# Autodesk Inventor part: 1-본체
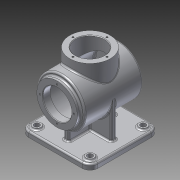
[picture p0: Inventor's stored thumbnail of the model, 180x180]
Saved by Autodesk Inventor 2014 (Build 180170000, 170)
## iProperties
Created: 2015-07
Part Number: 1-본체
Material: 알루미늄 6061
Document SubType Name: Modeling
Designer: Owner
Density: 2.71 g/cm^3
Appearance: 알루미늄 - 평지
Mass: 1277.64 g
Surface Area: 1267.64 cm^2
Volume: 471.455 cm^3
Author: Owner
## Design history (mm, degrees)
sketch "스케치1"
  geometry: C1 r 45 at (0, 0); 1 further point
  constraints: 1 centre point, 1 coincident
  dimensions: "d0" = 90 diameter of C1
extrude "돌출1" new body sketch "스케치1" stored distance "d1" = 110; taper "d2" = 0 deg
sketch "스케치2"
  geometry: C1 r 45 at (0, 0) reference; C2 r 38 at (0, 0)
  constraints: 1 centre point, 1 coincident
  dimensions: "d3" = 76 diameter of C2
extrude "돌출2" join sketch "스케치2" distance "d4" = 7; taper "d5" = 0 deg
node "작업 평면1"
sketch "스케치3"
  geometry: L1 (-65, 65)-(65, 65); L2 (65, 65)-(65, -65); L3 (65, -65)-(-65, -65); L4 (-65, -65)-(-65, 65); 3 further points
  constraints: 8 end point, 2 midpoint, 2 parallel, 1 horizontal, 1 horizontal alignment, 1 perpendicular, 1 vertical alignment
  dimensions: "d7" = 130 distance of L2.end L3.end; "d8" = 130 distance of L3.end L1.start
extrude "돌출3" join sketch "스케치3" distance "d9" = 10; taper "d10" = 0 deg
sketch "스케치4"
  geometry: L1 (-65, 65)-(-65, -65) reference; L2 (-45, 5)-(-5, 5); L3 (-5, 5)-(-5, 45); L4 (-5, 45)-(5, 45); L5 (5, 45)-(5, 5); L6 (5, 5)-(45, 5); L7 (45, 5)-(45, -5); L8 (45, -5)-(5, -5); L9 (5, -5)-(5, -45); L10 (5, -45)-(-5, -45); L11 (-5, -45)-(-5, -5); L12 (-5, -5)-(-45, -5); L13 (-45, -5)-(-45, 5); 4 further points
  constraints: 24 end point, 8 parallel, 7 equal length, 3 midpoint, 2 collinear, 2 perpendicular, 2 vertical alignment, 1 horizontal alignment
  dimensions: "d11" = 10 distance of L3.end L4.end; "d12" = 90 distance between parallel lines of L7 L13
extrude "돌출4" join sketch "스케치4" stored distance "d13" = 10; taper "d14" = 0 deg
sketch "스케치5"
  geometry: C1 r 7.5 at (-50, 50); C2 r 7.5 at (-50, -50); C3 r 7.5 at (50, -50); C4 r 7.5 at (50, 50); 1 further point
  constraints: 4 centre point, 2 horizontal alignment, 2 vertical alignment
  dimensions: "d15" = 15 diameter of C1; "d16" = 15 diameter of C2; "d17" = 15 diameter of C3; "d18" = 15 diameter of C4; "d19" = 100 distance of C4.centre C1.centre; "d20" = 50 horizontal distance of C4.centre point (0, 0); "d21" = 100 distance of C2.centre C1.centre; "d22" = 50 horizontal distance of point (0, 0) C1.centre
extrude "돌출5" join sketch "스케치5" distance "d23" = 3; taper "d24" = 0 deg
hole "구멍1" diameter "d27" = 10; stored, may be unused: countersink angle "d31" = 90 deg, drill point angle "d33" = 118 deg; dims "d25" = 10, "d26" = 10, "d28" = 6, "d29" = 4, "d30" = 2, "d32" = 8
hole "구멍2" diameter "d36" = 10; stored, may be unused: countersink angle "d40" = 90 deg, drill point angle "d42" = 118 deg; dims "d34" = 10, "d35" = 10, "d37" = 6, "d38" = 4, "d39" = 2, "d41" = 8
hole "구멍3" diameter "d45" = 10; stored, may be unused: countersink angle "d49" = 90 deg, drill point angle "d51" = 118 deg; dims "d43" = 10, "d44" = 10, "d46" = 6, "d47" = 4, "d48" = 2, "d50" = 8
hole "구멍4" diameter "d54" = 10; stored, may be unused: countersink angle "d58" = 90 deg, drill point angle "d60" = 118 deg; dims "d52" = 10, "d53" = 10, "d55" = 6, "d56" = 4, "d57" = 2, "d59" = 8
hole "구멍5" diameter "d63" = 54; stored, may be unused: countersink angle "d67" = 90 deg, drill point angle "d69" = 0 deg; dims "d61" = 10, "d62" = 10, "d64" = 6, "d65" = 4, "d66" = 2, "d68" = 14
hole "구멍6" diameter "d72" = 80; stored, may be unused: countersink angle "d76" = 90 deg, drill point angle "d78" = 0 deg; dims "d73" = 6, "d74" = 4, "d75" = 2, "d77" = 96, "d110" = 10, "d111" = 10
node "작업 평면2"
sketch "스케치7"
  geometry: C1 r 38 at (0, 0); 1 further point
  constraints: 1 centre point, 1 coincident
  dimensions: "d80" = 76 diameter of C1
extrude "돌출6" join sketch "스케치7" stored distance "d81" = 3; taper "d82" = 0 deg
sketch "스케치8"
  geometry: C1 r 38 at (0, 0) reference; C2 r 27 at (0, 0)
  constraints: 1 centre point, 1 coincident
  dimensions: "d83" = 54 diameter of C2
extrude "돌출7" cut sketch "스케치8" stored distance "d84" = 3; taper "d85" = 0 deg
sketch "스케치9"
  geometry: C1 r 27 at (0, 0) reference; 1 further point
  constraints: 1 vertical alignment
  dimensions: "d86" = 32 distance of C1.centre point (0, 32)
hole "구멍7" sketch "스케치9" at (0, 32) diameter "d87" = 3.242; stored, may be unused: countersink angle "d91" = 90 deg, drill point angle "d93" = 118 deg; dims "d88" = 8, "d89" = 4, "d90" = 2, "d92" = 10
sketch "스케치10"
  geometry: C1 r 27 at (0, 0) reference; 1 further point
  constraints: 1 horizontal alignment
  dimensions: "d97" = 32 distance of C1.centre point (32, 0)
hole "구멍8" sketch "스케치10" at (32, 0) diameter "d98" = 3.242; stored, may be unused: countersink angle "d102" = 90 deg, drill point angle "d104" = 118 deg; dims "d99" = 8, "d100" = 4, "d101" = 2, "d103" = 10
sketch "스케치11"
  geometry: C1 r 45 at (0, 0) reference; 1 further point
  constraints: 1 coincident, 1 other
extrude "돌출8" join sketch "스케치11" distance "d108" = 0.5; taper "d109" = 0 deg
fillet "모깎기1" dims "d112" = 15
chamfer "모따기1" distance "d113" = 1; stored, may be unused: second distance "d114" = 2, angle "d115" = 45 deg
fillet "모깎기2" dims "d116" = 3
fillet "모깎기3" dims "d117" = 3
fillet "모깎기4" dims "d118" = 3
fillet "모깎기5" dims "d119" = 3
fillet "모깎기6" dims "d120" = 3
fillet "모깎기7" dims "d121" = 3
fillet "모깎기8" dims "d122" = 3
fillet "모깎기9" dims "d123" = 3
fillet "모깎기10" dims "d124" = 3
node "솔리드1"
pattern_circular "원형 패턴1" dims angle "d95" = 360 deg
pattern_circular "원형 패턴2" dims angle "d106" = 360 deg
other parameters: "d6" = -78
